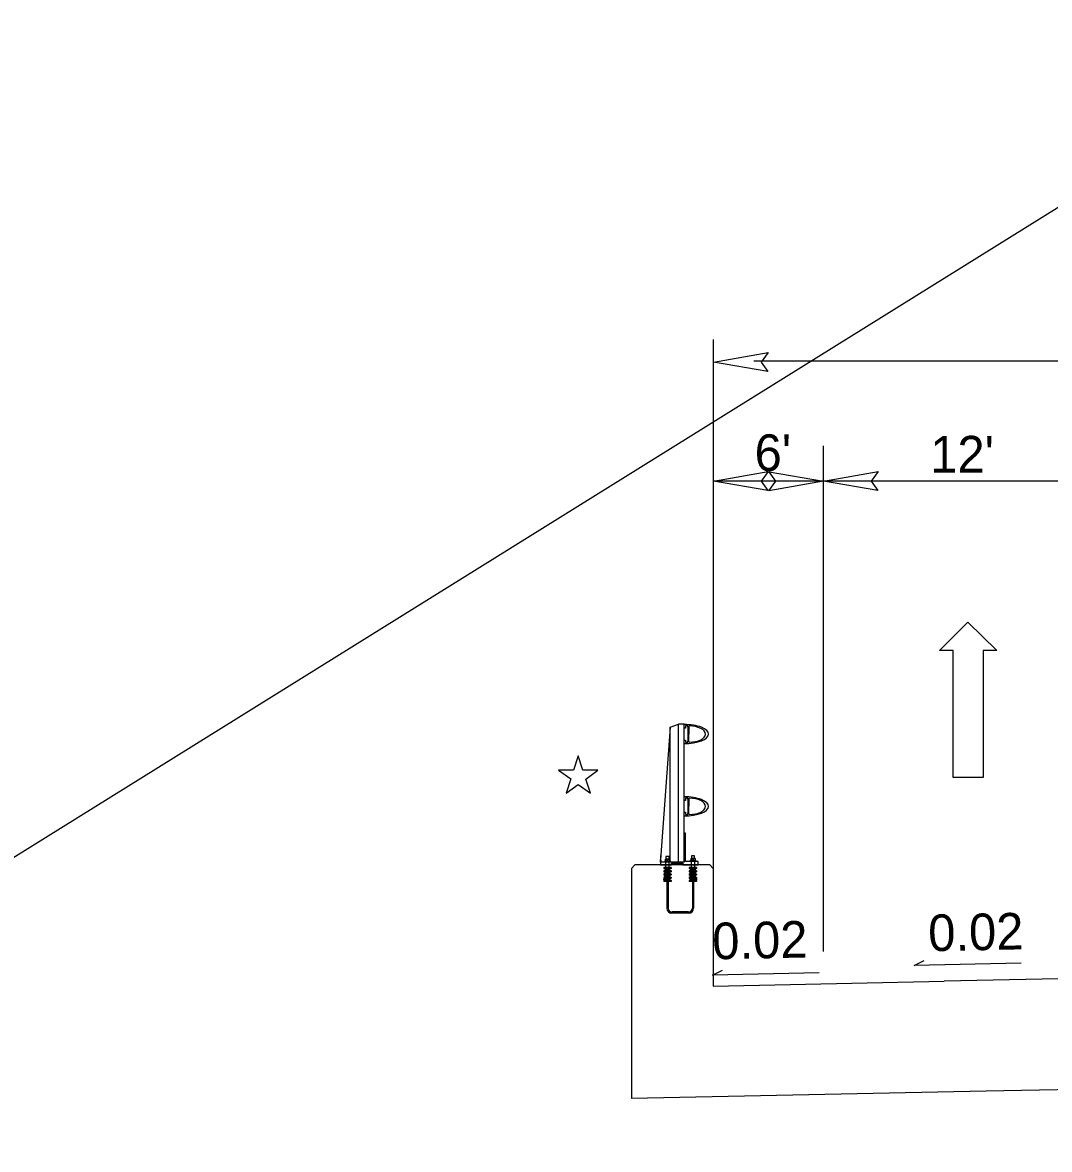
# Model space of a CAD drawing. Extents: x 573813 to 575363, y -54752 to -53123.
# Drawn here: x 573929.6 to 573985.7, y -54418.1 to -54356.6 of the extents above; entities that cross this region are included whole.
import ezdxf

# ---------------------------------------------------------------- set-up
doc = ezdxf.new("R2010")
doc.units = 0
for name, color, linetype in [('Old_Level_1', 7, 'Continuous'), ('Old_Level_11', 7, 'Continuous'), ('Old_Level_4', 7, 'Continuous'), ('Prop RDY Traffic Signal CELL', 7, 'Continuous'), ('Typical Bridge Rail Two Bar CELL', 7, 'Continuous')]:
    doc.layers.add(name, color=color, linetype=linetype)

msp = doc.modelspace()

# ---------------------------------------------------------------- linework, layer by layer
at = {"layer": 'Old_Level_1'}
for p, q in [((573978.314, -54408.084), (573978.865, -54407.809)), ((573967.285, -54408.613), (573967.836, -54408.338)), ((573973.123, -54408.492), (573967.285, -54408.613)), ((573984.153, -54407.962), (573978.314, -54408.084)), ((573967.334, -54409.211), (573979.952, -54408.948)), ((573989.851, -54408.742), (573979.952, -54408.948)), ((574002.012, -54414.546), (573982.246, -54414.957)), ((573982.246, -54414.956), (573962.862, -54415.358))]:
    msp.add_line(p, q, dxfattribs=at)
at = {"layer": 'Old_Level_11'}
for p, q in [((574191.398, -54239.044), (573813.441, -54474.11)), ((573967.35, -54407.357), (573967.351, -54373.884)), ((574034.355, -54375.077), (573969.553, -54375.077)), ((573973.35, -54407.324), (573973.351, -54379.703)), ((573973.35, -54381.626), (573967.35, -54381.626)), ((573989.851, -54381.626), (573973.35, -54381.626))]:
    msp.add_line(p, q, dxfattribs=at)
for points in [[(573970.32, -54375.632), (573967.351, -54375.121), (573970.337, -54374.593), (573969.958, -54375.121)], [(573970.32, -54382.137), (573967.35, -54381.626), (573970.337, -54381.098), (573969.957, -54381.626)], [(573970.38, -54381.114), (573973.35, -54381.626), (573970.364, -54382.154), (573970.743, -54381.626)], [(573976.32, -54382.137), (573973.35, -54381.626), (573976.337, -54381.098), (573975.957, -54381.626)]]:
    msp.add_lwpolyline(points, close=True, dxfattribs=at)
at = {"layer": 'Old_Level_4'}
for p, q in [((573979.702, -54390.883), (573981.236, -54389.324)), ((573981.236, -54389.324), (573982.82, -54390.883)), ((573980.444, -54390.883), (573979.702, -54390.883)), ((573980.444, -54397.814), (573980.444, -54390.883)), ((573982.82, -54390.883), (573982.078, -54390.883)), ((573982.078, -54390.883), (573982.078, -54397.813)), ((573982.078, -54397.813), (573980.444, -54397.814))]:
    msp.add_line(p, q, dxfattribs=at)
at = {"layer": 'Prop RDY Traffic Signal CELL'}
msp.add_lwpolyline([(573959.702, -54397.418), (573958.886, -54397.418), (573959.547, -54397.897), (573959.294, -54398.675), (573959.956, -54398.194), (573960.617, -54398.675), (573960.364, -54397.898), (573961.025, -54397.417), (573960.208, -54397.418), (573959.955, -54396.64), (573959.702, -54397.418)], dxfattribs=at)
at = {"layer": 'Typical Bridge Rail Two Bar CELL'}
for p, q in [((573964.982, -54395.057), (573965.438, -54394.908)), ((573965.739, -54394.908), (573965.438, -54394.908)), ((573965.438, -54402.442), (573965.438, -54394.908)), ((573965.739, -54402.442), (573965.739, -54394.908)), ((573964.982, -54395.057), (573964.457, -54402.292)), ((573964.982, -54402.442), (573964.982, -54395.057)), ((573965.991, -54395.033), (573965.991, -54395.442)), ((573965.991, -54395.852), (573965.991, -54395.442)), ((573964.982, -54398.514), (573964.966, -54398.514)), ((573965.991, -54398.982), (573965.991, -54399.39)), ((573965.991, -54399.8), (573965.991, -54399.39)), ((573964.457, -54402.442), (573964.457, -54402.292)), ((573964.47, -54402.207), (573964.47, -54402.075)), ((573964.921, -54402.138), (573964.75, -54402.138)), ((573964.75, -54402.138), (573964.75, -54402.279)), ((573964.921, -54402.279), (573964.921, -54402.138)), ((573966.317, -54402.098), (573966.145, -54402.098)), ((573966.145, -54402.098), (573966.145, -54402.24)), ((573966.317, -54402.24), (573966.317, -54402.098)), ((573962.862, -54402.788), (573963.057, -54402.593)), ((573962.862, -54402.788), (573962.862, -54415.358)), ((573967.139, -54402.593), (573963.057, -54402.593)), ((573965.031, -54402.738), (573964.63, -54402.738)), ((573965.031, -54402.782), (573964.63, -54402.782)), ((573964.797, -54402.915), (573964.63, -54402.915)), ((573964.797, -54402.96), (573964.63, -54402.96)), ((573964.797, -54402.827), (573964.719, -54402.827)), ((573964.797, -54402.871), (573964.719, -54402.871)), ((573964.746, -54402.776), (573964.746, -54402.442)), ((573964.864, -54402.826), (573964.797, -54402.826)), ((573964.797, -54402.826), (573964.797, -54404.949)), ((573964.864, -54402.826), (573964.864, -54404.949)), ((573964.942, -54402.827), (573964.864, -54402.827)), ((573964.942, -54402.871), (573964.864, -54402.871)), ((573965.031, -54402.915), (573964.864, -54402.915)), ((573965.031, -54402.96), (573964.864, -54402.96)), ((573964.92, -54402.776), (573964.92, -54402.442)), ((573966.424, -54402.738), (573966.024, -54402.738)), ((573966.424, -54402.782), (573966.024, -54402.782)), ((573966.191, -54402.915), (573966.024, -54402.915)), ((573966.191, -54402.96), (573966.024, -54402.96)), ((573966.191, -54402.827), (573966.113, -54402.827)), ((573966.191, -54402.871), (573966.113, -54402.871)), ((573966.136, -54402.738), (573966.136, -54402.404)), ((573966.191, -54402.826), (573966.191, -54404.949)), ((573966.258, -54402.827), (573966.191, -54402.827)), ((573966.258, -54402.826), (573966.258, -54404.949)), ((573966.336, -54402.827), (573966.258, -54402.827)), ((573966.336, -54402.871), (573966.258, -54402.871)), ((573966.424, -54402.915), (573966.258, -54402.915)), ((573966.424, -54402.96), (573966.258, -54402.96)), ((573966.325, -54402.738), (573966.325, -54402.404)), ((573967.139, -54402.593), (573967.334, -54402.788)), ((573967.334, -54402.788), (573967.334, -54409.211)), ((573964.797, -54403.093), (573964.63, -54403.093)), ((573964.797, -54403.138), (573964.63, -54403.138)), ((573964.797, -54403.271), (573964.63, -54403.271)), ((573964.797, -54403.315), (573964.63, -54403.315)), ((573964.797, -54403.448), (573964.63, -54403.448)), ((573964.797, -54403.492), (573964.63, -54403.492)), ((573964.797, -54403.005), (573964.719, -54403.005)), ((573964.797, -54403.049), (573964.719, -54403.049)), ((573964.797, -54403.182), (573964.719, -54403.182)), ((573964.797, -54403.227), (573964.719, -54403.227)), ((573964.797, -54403.36), (573964.719, -54403.36)), ((573964.797, -54403.404), (573964.719, -54403.404)), ((573964.942, -54403.005), (573964.864, -54403.005)), ((573964.942, -54403.049), (573964.864, -54403.049)), ((573965.031, -54403.093), (573964.864, -54403.093)), ((573965.031, -54403.138), (573964.864, -54403.138)), ((573964.942, -54403.182), (573964.864, -54403.182)), ((573964.942, -54403.227), (573964.864, -54403.227)), ((573965.031, -54403.271), (573964.864, -54403.271)), ((573965.031, -54403.315), (573964.864, -54403.315)), ((573964.942, -54403.36), (573964.864, -54403.36)), ((573964.942, -54403.404), (573964.864, -54403.404)), ((573965.031, -54403.448), (573964.864, -54403.448)), ((573965.031, -54403.492), (573964.864, -54403.492)), ((573966.191, -54403.093), (573966.024, -54403.093)), ((573966.191, -54403.138), (573966.024, -54403.138)), ((573966.191, -54403.271), (573966.024, -54403.271)), ((573966.191, -54403.315), (573966.024, -54403.315)), ((573966.191, -54403.448), (573966.024, -54403.448)), ((573966.191, -54403.492), (573966.024, -54403.492)), ((573966.191, -54403.005), (573966.113, -54403.005)), ((573966.191, -54403.049), (573966.113, -54403.049)), ((573966.191, -54403.182), (573966.113, -54403.182)), ((573966.191, -54403.227), (573966.113, -54403.227)), ((573966.191, -54403.36), (573966.113, -54403.36)), ((573966.191, -54403.404), (573966.113, -54403.404)), ((573966.336, -54403.005), (573966.258, -54403.005)), ((573966.336, -54403.049), (573966.258, -54403.049)), ((573966.424, -54403.093), (573966.258, -54403.093)), ((573966.424, -54403.138), (573966.258, -54403.138)), ((573966.336, -54403.182), (573966.258, -54403.182)), ((573966.336, -54403.227), (573966.258, -54403.227)), ((573966.424, -54403.271), (573966.258, -54403.271)), ((573966.424, -54403.315), (573966.258, -54403.315)), ((573966.336, -54403.36), (573966.258, -54403.36)), ((573966.336, -54403.404), (573966.258, -54403.404)), ((573966.424, -54403.448), (573966.258, -54403.448)), ((573966.424, -54403.492), (573966.258, -54403.492)), ((573965.978, -54405.162), (573965.078, -54405.162)), ((573965.978, -54405.228), (573965.078, -54405.228))]:
    msp.add_line(p, q, dxfattribs=at)
for points in [[(573965.739, -54395.964), (573965.739, -54395.768), (573965.82, -54395.768), (573965.82, -54395.801), (573965.812, -54395.801), (573965.812, -54395.883), (573965.942, -54395.883), (573965.958, -54395.757), (573965.958, -54395.442), (573965.958, -54395.127), (573965.942, -54395.001), (573965.812, -54395.001), (573965.812, -54395.083), (573965.82, -54395.083), (573965.82, -54395.116), (573965.739, -54395.116), (573965.739, -54394.919)], [(573965.739, -54399.913), (573965.739, -54399.717), (573965.82, -54399.717), (573965.82, -54399.749), (573965.812, -54399.749), (573965.812, -54399.831), (573965.942, -54399.831), (573965.958, -54399.705), (573965.958, -54399.39), (573965.958, -54399.075), (573965.942, -54398.951), (573965.812, -54398.951), (573965.812, -54399.031), (573965.82, -54399.031), (573965.82, -54399.064), (573965.739, -54399.064), (573965.739, -54398.869)], [(573966.511, -54402.593), (573966.511, -54402.404), (573965.815, -54402.404), (573965.815, -54400.858), (573965.739, -54400.858), (573965.739, -54402.442), (573964.492, -54402.442), (573964.492, -54402.331), (573964.457, -54402.331), (573964.457, -54402.593), (573965.058, -54402.593), (573965.058, -54402.488), (573965.664, -54402.488), (573965.664, -54402.593), (573966.511, -54402.593)], [(573964.962, -54402.41), (573964.962, -54402.301), (573964.94, -54402.279), (573964.73, -54402.279), (573964.707, -54402.301), (573964.707, -54402.41), (573964.962, -54402.41), (573964.877, -54402.41), (573964.877, -54402.301), (573964.899, -54402.279), (573964.877, -54402.301), (573964.857, -54402.279), (573964.813, -54402.279), (573964.792, -54402.301), (573964.792, -54402.41), (573964.792, -54402.301), (573964.77, -54402.279)], [(573966.358, -54402.372), (573966.358, -54402.263), (573966.338, -54402.241), (573966.125, -54402.241), (573966.103, -54402.263), (573966.103, -54402.372), (573966.358, -54402.372), (573966.272, -54402.372), (573966.272, -54402.263), (573966.295, -54402.241), (573966.272, -54402.263), (573966.252, -54402.241), (573966.208, -54402.241), (573966.188, -54402.263), (573966.188, -54402.372), (573966.188, -54402.263), (573966.167, -54402.241)], [(573964.63, -54402.738), (573964.63, -54402.782), (573964.719, -54402.827), (573964.719, -54402.871), (573964.63, -54402.915), (573964.63, -54402.96), (573964.719, -54403.005), (573964.719, -54403.049), (573964.63, -54403.093), (573964.63, -54403.138), (573964.719, -54403.182), (573964.719, -54403.227), (573964.63, -54403.271), (573964.63, -54403.315), (573964.719, -54403.36), (573964.719, -54403.404), (573964.63, -54403.448), (573964.63, -54403.492)], [(573965.006, -54402.444), (573965.006, -54402.41), (573964.835, -54402.41), (573964.663, -54402.41), (573964.663, -54402.444)], [(573965.031, -54402.738), (573965.031, -54402.782), (573964.943, -54402.827), (573964.943, -54402.871), (573965.031, -54402.915), (573965.031, -54402.96), (573964.943, -54403.005), (573964.943, -54403.049), (573965.031, -54403.093), (573965.031, -54403.138), (573964.943, -54403.182), (573964.943, -54403.227), (573965.031, -54403.271), (573965.031, -54403.315), (573964.943, -54403.36), (573964.943, -54403.404), (573965.031, -54403.448), (573965.031, -54403.492)], [(573966.024, -54402.738), (573966.024, -54402.782), (573966.113, -54402.827), (573966.113, -54402.871), (573966.024, -54402.915), (573966.024, -54402.96), (573966.113, -54403.005), (573966.113, -54403.049), (573966.024, -54403.093), (573966.024, -54403.138), (573966.113, -54403.182), (573966.113, -54403.227), (573966.024, -54403.271), (573966.024, -54403.315), (573966.113, -54403.36), (573966.113, -54403.404), (573966.024, -54403.448), (573966.024, -54403.492)], [(573966.406, -54402.405), (573966.406, -54402.371), (573966.233, -54402.371), (573966.06, -54402.371), (573966.06, -54402.405)], [(573966.426, -54402.738), (573966.426, -54402.782), (573966.336, -54402.827), (573966.336, -54402.871), (573966.426, -54402.915), (573966.426, -54402.96), (573966.336, -54403.005), (573966.336, -54403.049), (573966.426, -54403.093), (573966.426, -54403.138), (573966.336, -54403.182), (573966.336, -54403.227), (573966.426, -54403.271), (573966.426, -54403.315), (573966.336, -54403.36), (573966.336, -54403.404), (573966.426, -54403.448), (573966.426, -54403.492)]]:
    msp.add_lwpolyline(points, dxfattribs=at)
for centre in [(573964.665, -54403.382), (573966.39, -54403.382)]:
    msp.add_circle(centre, 0.0334, dxfattribs=at)
for centre, radius, start, end in [((573966.023, -54395.033), 0.0313, 90, 180), ((573966.023, -54395.851), 0.0313, 180, 270), ((573966.023, -54398.982), 0.0313, 90, 180), ((573966.023, -54399.8), 0.0313, 180, 270), ((573965.078, -54404.949), 0.28, 180, 270), ((573965.078, -54404.949), 0.214, 180, 269.99996), ((573965.978, -54404.949), 0.214, 270, 0), ((573965.978, -54404.949), 0.28, 270, 0)]:
    msp.add_arc(centre, radius, start, end, dxfattribs=at)
for centre, major_axis, ratio, start_param, end_param in [((573965.738, -54395.442), (1.338, 0), 0.39036, 6.282787, 7.853967), ((573965.738, -54395.442), (1.338, 0), 0.39036, 4.712404, 6.282787), ((573966.023, -54395.442), (0.889, 0), 0.495501, 6.282718, 7.853881), ((573966.023, -54395.442), (0.889, 0), 0.495501, 4.712489, 6.282718), ((573965.738, -54399.391), (1.338, 0), 0.39036, 6.282787, 7.853967), ((573966.023, -54399.391), (0.889, 0), 0.495501, 6.282718, 7.853881), ((573965.738, -54399.391), (1.338, 0), 0.39036, 4.712404, 6.282787), ((573966.023, -54399.391), (0.889, 0), 0.495501, 4.712489, 6.282718)]:
    msp.add_ellipse(centre, major_axis=major_axis, ratio=ratio, start_param=start_param, end_param=end_param, dxfattribs=at)

# ---------------------------------------------------------------- texts
at = {"layer": 'Old_Level_1'}
for p in [(573979.097, -54407.308), (573967.298, -54407.752)]:
    msp.add_text('0.02', height=2, rotation=1.19184, dxfattribs=at).set_placement(p)
at = {"layer": 'Old_Level_11'}
for s, p in [("6'", (573969.591, -54381.072)), ("12'", (573979.186, -54381.156))]:
    msp.add_text(s, height=2, rotation=359.99991, dxfattribs=at).set_placement(p)

doc.saveas('drawing.dxf')
